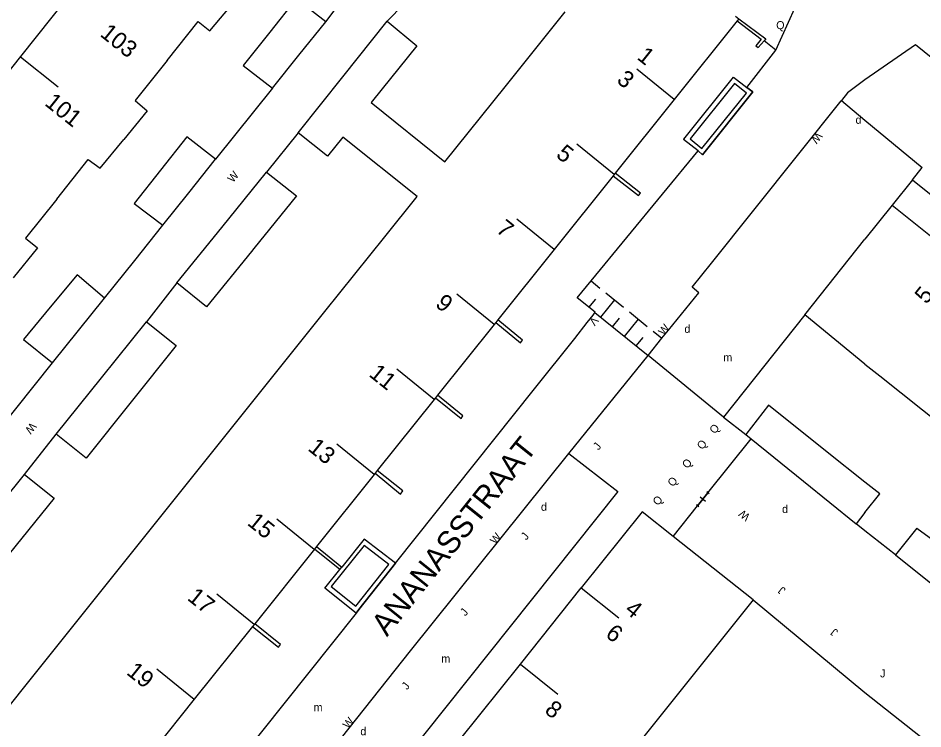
# Model space of a CAD drawing. Extents: x 134999 to 136502, y 457398 to 459002.
# Drawn here: x 135447.1 to 135503.6, y 457998 to 458042.3 of the extents above; entities that cross this region are included whole.
import ezdxf

# ---------------------------------------------------------------- set-up
doc = ezdxf.new("R2010")
doc.units = 0
for name, color, linetype in [('RI_DGTB_15', 7, 'Continuous'), ('RI_DGTB_29', 7, 'Continuous'), ('RI_DGTB_3', 7, 'Continuous'), ('RI_DGTB_30', 7, 'Continuous'), ('RI_DGTB_31', 7, 'Continuous'), ('RI_DGTB_35', 7, 'Continuous'), ('RI_DGTB_36', 7, 'Continuous'), ('RI_DGTB_37', 7, 'Continuous'), ('RI_DGTB_4', 7, 'Continuous'), ('RI_DGTB_43', 7, 'Continuous'), ('RI_DGTB_48', 7, 'Continuous'), ('RI_DGTB_5', 7, 'Continuous'), ('RI_DGTB_53', 7, 'Continuous'), ('RI_DGTB_54', 7, 'Continuous'), ('RI_DGTB_6', 7, 'Continuous')]:
    doc.layers.add(name, color=color, linetype=linetype)

msp = doc.modelspace()

# ---------------------------------------------------------------- linework, layer by layer
at = {"layer": 'RI_DGTB_15'}
for p, q in [((135447.257, 458039.913), (135449.6, 458038.04)), ((135488.09, 458037.25), (135485.749, 458039.126)), ((135484.342, 458032.569), (135482.001, 458034.445)), ((135480.594, 458027.888), (135478.253, 458029.764)), ((135476.846, 458023.207), (135474.505, 458025.083)), ((135473.098, 458018.526), (135470.757, 458020.402)), ((135469.35, 458013.845), (135467.009, 458015.721)), ((135465.602, 458009.164), (135463.261, 458011.04)), ((135482.275, 458006.757), (135484.619, 458004.884)), ((135461.854, 458004.483), (135459.513, 458006.359)), ((135458.106, 457999.802), (135455.765, 458001.678)), ((135478.476, 458002.005), (135480.82, 458000.132))]:
    msp.add_line(p, q, dxfattribs=at)
at = {"layer": 'RI_DGTB_3'}
for p, q in [((135501.696, 458030.642), (135500, 458028.523)), ((135501.696, 458030.642), (135506.429, 458026.857)), ((135500, 458020.732), (135500.934, 458019.985)), ((135500.934, 458019.985), (135505.666, 458016.202))]:
    msp.add_line(p, q, dxfattribs=at)
at = {"layer": 'RI_DGTB_31'}
for p, q in [((135492.988, 458037.71), (135489.857, 458033.797)), ((135492.614, 458037.993), (135492.988, 458037.71)), ((135488.673, 458034.74), (135488.694, 458034.766)), ((135489.591, 458034.029), (135488.673, 458034.74)), ((135489.857, 458033.797), (135489.591, 458034.029)), ((135482.894, 458025.924), (135483.447, 458025.475)), ((135482.761, 458024.252), (135483.197, 458024.789)), ((135483.499, 458023.654), (135484.37, 458024.728)), ((135483.816, 458025.176), (135484.923, 458024.279)), ((135483.137, 458023.947), (135486.451, 458021.261)), ((135484.237, 458023.056), (135484.672, 458023.593)), ((135485.292, 458023.98), (135486.399, 458023.083)), ((135484.975, 458022.458), (135485.845, 458023.531)), ((135486.768, 458022.784), (135487.321, 458022.335)), ((135485.713, 458021.86), (135486.148, 458022.396)), ((135470.678, 458008.298), (135468.393, 458005.41)), ((135468.393, 458005.41), (135468.21, 458005.179))]:
    msp.add_line(p, q, dxfattribs=at)
for points in [[(135488.694, 458034.766), (135491.78, 458038.639), (135492.614, 458037.993)], [(135489.079, 458034.783), (135489.82, 458034.191), (135492.601, 458037.629), (135491.853, 458038.247), (135489.079, 458034.783)], [(135470.678, 458008.298), (135468.724, 458009.8), (135467.326, 458008.058)], [(135466.658, 458006.836), (135468.19, 458005.619), (135470.255, 458008.221), (135468.723, 458009.413), (135466.658, 458006.836)], [(135468.21, 458005.179), (135466.264, 458006.735), (135467.202, 458007.904)]]:
    msp.add_lwpolyline(points, dxfattribs=at)
at = {"layer": 'RI_DGTB_4'}
for p, q in [((135450.7, 458044.243), (135447.245, 458039.922)), ((135477.517, 458038.039), (135481.267, 458042.718)), ((135491.91, 458042.449), (135492.12, 458042.282)), ((135492.12, 458042.282), (135492.019, 458042.156)), ((135492.019, 458042.156), (135488.09, 458037.25)), ((135447.245, 458039.922), (135443.791, 458035.602)), ((135473.767, 458033.359), (135477.517, 458038.039)), ((135488.09, 458037.25), (135484.401, 458032.642)), ((135484.401, 458032.642), (135484.342, 458032.57)), ((135484.276, 458032.486), (135480.594, 458027.888)), ((135484.342, 458032.57), (135484.276, 458032.486)), ((135466.268, 458024), (135470.017, 458028.679)), ((135496.252, 458023.792), (135500, 458028.523)), ((135480.594, 458027.888), (135477.066, 458023.482)), ((135462.518, 458019.32), (135466.268, 458024)), ((135500, 458020.732), (135496.252, 458023.792)), ((135476.846, 458023.207), (135473.297, 458018.778)), ((135476.941, 458023.326), (135476.846, 458023.207)), ((135477.066, 458023.482), (135476.941, 458023.326)), ((135458.768, 458014.64), (135462.518, 458019.32)), ((135473.096, 458018.527), (135469.537, 458014.079)), ((135473.165, 458018.613), (135473.096, 458018.527)), ((135473.297, 458018.778), (135473.165, 458018.613)), ((135455.019, 458009.961), (135458.768, 458014.64)), ((135469.537, 458014.079), (135469.402, 458013.91)), ((135469.35, 458013.845), (135465.743, 458009.34)), ((135469.402, 458013.91), (135469.35, 458013.845)), ((135451.268, 458005.281), (135455.019, 458009.961)), ((135493.016, 458006.014), (135488.019, 458009.966)), ((135465.618, 458009.184), (135461.883, 458004.521)), ((135465.743, 458009.34), (135465.618, 458009.184)), ((135478.477, 458002.004), (135482.277, 458006.756)), ((135493.016, 458006.014), (135489.184, 458001.237)), ((135447.519, 458000.602), (135451.268, 458005.281)), ((135461.883, 458004.521), (135461.74, 458004.342)), ((135461.74, 458004.342), (135458.105, 457999.803)), ((135474.678, 457997.252), (135478.477, 458002.004)), ((135489.184, 458001.237), (135485.376, 457996.491)), ((135443.769, 457995.922), (135447.519, 458000.602)), ((135458.105, 457999.803), (135454.357, 457995.122))]:
    msp.add_line(p, q, dxfattribs=at)
for points in [[(135470.017, 458028.679), (135472.027, 458031.187)], [(135488.019, 458009.966), (135486.074, 458011.505), (135482.277, 458006.756)]]:
    msp.add_lwpolyline(points, dxfattribs=at)
at = {"layer": 'RI_DGTB_48'}
for p, q in [((135467.202, 458007.904), (135465.618, 458009.184)), ((135465.743, 458009.34), (135467.326, 458008.058)), ((135467.202, 458007.904), (135467.326, 458008.058))]:
    msp.add_line(p, q, dxfattribs=at)
for points in [[(135492.12, 458042.282), (135493.815, 458041.027), (135493.712, 458040.906)], [(135492.019, 458042.156), (135493.519, 458040.999), (135493.191, 458040.591), (135493.335, 458040.477), (135493.712, 458040.906)], [(135484.276, 458032.486), (135485.862, 458031.242), (135485.987, 458031.397), (135484.401, 458032.642)], [(135476.941, 458023.326), (135478.492, 458022.053), (135478.618, 458022.215), (135477.066, 458023.482)], [(135473.165, 458018.613), (135474.771, 458017.335), (135474.886, 458017.487), (135473.297, 458018.778)], [(135469.402, 458013.91), (135470.992, 458012.611), (135471.145, 458012.808), (135469.537, 458014.079)], [(135461.74, 458004.342), (135463.363, 458003.069), (135463.485, 458003.234), (135461.883, 458004.521)]]:
    msp.add_lwpolyline(points, dxfattribs=at)
at = {"layer": 'RI_DGTB_5'}
for p, q in [((135469.147, 458037.061), (135473.767, 458033.359)), ((135472.027, 458031.187), (135467.395, 458034.898))]:
    msp.add_line(p, q, dxfattribs=at)
for points in [[(135456.415, 458039.674), (135458.353, 458042.104), (135459.076, 458041.518), (135460.649, 458043.371)], [(135456.415, 458039.674), (135454.416, 458037.169), (135455.168, 458036.53), (135453.712, 458034.753)], [(135449.516, 458031.025), (135451.488, 458033.497), (135452.239, 458032.954), (135453.712, 458034.753)], [(135449.516, 458031.025), (135447.574, 458028.589), (135448.313, 458027.983), (135446.806, 458026.11)]]:
    msp.add_lwpolyline(points, dxfattribs=at)
at = {"layer": 'RI_DGTB_53'}
for p, q in [((135490.409, 458027.036), (135498.502, 458037.149)), ((135498.527, 458037.181), (135500, 458035.96)), ((135500, 458035.96), (135503.576, 458032.995)), ((135502.963, 458032.227), (135501.696, 458030.642)), ((135496.252, 458023.792), (135491.165, 458017.412)), ((135491.165, 458017.412), (135492.565, 458016.341)), ((135490.193, 458012.686), (135492.899, 458016.07)), ((135489.549, 458011.88), (135490.194, 458012.687)), ((135490.193, 458012.686), (135489.549, 458011.88)), ((135490.033, 458012.154), (135489.709, 458012.412)), ((135490.274, 458012.623), (135490.114, 458012.751)), ((135488.019, 458009.966), (135489.549, 458011.88)), ((135489.629, 458011.816), (135489.469, 458011.944)), ((135500, 458010.325), (135499.442, 458010.767)), ((135501.904, 458008.818), (135500, 458010.325))]:
    msp.add_line(p, q, dxfattribs=at)
for points in [[(135506.201, 458038.203), (135503.146, 458040.643), (135500, 458038.47)], [(135502.963, 458032.227), (135540.814, 458001.934), (135539.56, 458000.364)]]:
    msp.add_lwpolyline(points, dxfattribs=at)
at = {"layer": 'RI_DGTB_54'}
for p, q in [((135466.321, 458042.095), (135469.789, 458046.684)), ((135494.441, 458040.321), (135493.712, 458040.906)), ((135492.614, 458037.993), (135494.441, 458040.321)), ((135462.987, 458037.941), (135459.441, 458033.511)), ((135489.857, 458033.797), (135492.988, 458037.71)), ((135492.988, 458037.71), (135492.614, 458037.993)), ((135498.502, 458037.149), (135498.527, 458037.181)), ((135464.604, 458035.17), (135462.622, 458032.713)), ((135488.673, 458034.74), (135488.694, 458034.766)), ((135489.591, 458034.029), (135489.857, 458033.797)), ((135502.963, 458032.227), (135503.576, 458032.995)), ((135454.404, 458027.2), (135456.144, 458029.398)), ((135452.506, 458024.842), (135454.404, 458027.2)), ((135489.204, 458025.53), (135490.409, 458027.036)), ((135457.021, 458025.793), (135455.128, 458023.374)), ((135445.634, 458016.287), (135449.255, 458020.803)), ((135481.502, 458015.147), (135486.451, 458021.261)), ((135491.165, 458017.412), (135486.451, 458021.261)), ((135447.507, 458013.838), (135449.482, 458016.346)), ((135468.393, 458005.41), (135470.678, 458008.298)), ((135493.016, 458006.014), (135500, 458000.229)), ((135468.21, 458005.179), (135468.393, 458005.41)), ((135500, 458000.229), (135504.365, 457996.786))]:
    msp.add_line(p, q, dxfattribs=at)
for points in [[(135494.441, 458040.321), (135496.809, 458045.594), (135496.966, 458047.987), (135494.208, 458050.252)], [(135470.992, 458045.337), (135470.019, 458044.154), (135471.204, 458043.201), (135470.165, 458042.122)], [(135500, 458038.47), (135498.908, 458037.66), (135498.527, 458037.181)], [(135482.894, 458025.924), (135489.591, 458034.029)], [(135483.157, 458023.974), (135482.017, 458024.863), (135482.894, 458025.924)], [(135487.73, 458022.839), (135489.622, 458025.173), (135489.204, 458025.53)], [(135470.678, 458008.298), (135479.367, 458019.191), (135481.876, 458022.315), (135482.653, 458023.322), (135483.016, 458023.784), (135483.157, 458023.974)], [(135487.321, 458022.335), (135487.73, 458022.839)], [(135486.451, 458021.261), (135487.321, 458022.335)], [(135481.502, 458015.147), (135484.555, 458012.773), (135461.76, 457984.216), (135458.729, 457986.601)], [(135462.605, 457991.477), (135471.61, 458002.822), (135481.502, 458015.147)], [(135468.21, 458005.179), (135459.351, 457994.078)]]:
    msp.add_lwpolyline(points, dxfattribs=at)
at = {"layer": 'RI_DGTB_6'}
for p, q in [((135464.49, 458031.237), (135461.828, 458027.931)), ((135492.565, 458016.341), (135492.899, 458016.07)), ((135500, 458011.469), (135499.442, 458010.767)), ((135503.24, 458010.484), (135506.79, 458007.883))]:
    msp.add_line(p, q, dxfattribs=at)
for points in [[(135466.321, 458042.095), (135464.481, 458043.539), (135462.82, 458041.454)], [(135464.642, 458040.003), (135466.321, 458042.095)], [(135467.384, 458038.646), (135470.165, 458042.122)], [(135470.165, 458042.122), (135472.014, 458040.6), (135469.233, 458037.167)], [(135462.82, 458041.454), (135461.16, 458039.37), (135462.987, 458037.941)], [(135462.987, 458037.941), (135464.642, 458040.003)], [(135464.604, 458035.17), (135467.384, 458038.646)], [(135469.233, 458037.167), (135469.147, 458037.061)], [(135459.441, 458033.511), (135457.652, 458034.909), (135456, 458032.83)], [(135467.395, 458034.898), (135466.427, 458033.704), (135464.604, 458035.17)], [(135457.768, 458031.425), (135459.441, 458033.511)], [(135456, 458032.83), (135454.348, 458030.75), (135456.144, 458029.398)], [(135459.822, 458029.253), (135462.622, 458032.713)], [(135462.622, 458032.713), (135464.49, 458031.237)], [(135456.144, 458029.398), (135457.768, 458031.425)], [(135457.021, 458025.793), (135459.822, 458029.253)], [(135461.68, 458027.749), (135458.877, 458024.295), (135457.021, 458025.793)], [(135461.828, 458027.931), (135461.68, 458027.749)], [(135452.506, 458024.842), (135450.784, 458026.303), (135449.11, 458024.283)], [(135450.878, 458022.82), (135452.506, 458024.842)], [(135449.11, 458024.283), (135447.437, 458022.263), (135449.255, 458020.803)], [(135452.305, 458019.86), (135455.128, 458023.374)], [(135455.128, 458023.374), (135456.972, 458021.883), (135454.164, 458018.369)], [(135449.255, 458020.803), (135450.878, 458022.82)], [(135449.482, 458016.346), (135452.305, 458019.86)], [(135454.164, 458018.369), (135451.351, 458014.848), (135449.482, 458016.346)], [(135497.643, 458015.235), (135493.979, 458018.159), (135492.565, 458016.341)], [(135492.899, 458016.07), (135496.17, 458013.419)], [(135500, 458013.355), (135497.643, 458015.235)], [(135444.7, 458010.365), (135447.507, 458013.838)], [(135447.507, 458013.838), (135449.356, 458012.366), (135446.545, 458008.874)], [(135496.17, 458013.419), (135499.442, 458010.767)], [(135500, 458011.469), (135500.918, 458012.623), (135500, 458013.355)], [(135503.24, 458010.484), (135501.904, 458008.818)], [(135501.904, 458008.818), (135505.371, 458006.046)]]:
    msp.add_lwpolyline(points, dxfattribs=at)

# ---------------------------------------------------------------- texts
at = {"layer": 'RI_DGTB_29'}
for p in [(135499.411, 458035.726), (135488.722, 458022.681), (135479.762, 458011.571), (135494.82, 458011.432), (135468.482, 457997.561)]:
    msp.add_text('d', height=0.5, dxfattribs=at).set_placement(p)
at = {"layer": 'RI_DGTB_30'}
for s, height, rotation, p in [('W', 0.5, 231.3952, (135496.991, 458035.243)), ('W', 0.5, 50.404, (135460.525, 458032.017)), ('V', 0.499, 231.3241, (135483.015, 458023.73)), ('W', 0.5, 51.3952, (135487.44, 458022.477)), ('W', 0.499, 231.2576, (135447.903, 458017.121)), ('W', 0.499, 141.5806, (135492.867, 458011.28)), ('W', 0.5, 51.3952, (135476.924, 458009.441)), ('W', 0.5, 51.3952, (135467.729, 457997.933))]:
    msp.add_text(s, height=height, rotation=rotation, dxfattribs=at).set_placement(p)
at = {"layer": 'RI_DGTB_31'}
for s, p in [('Q', (135494.454, 458041.632)), ('J', (135500.942, 458001.171))]:
    msp.add_text(s, height=0.5, dxfattribs=at).set_placement(p)
for s, height, rotation, p in [('Q', 0.5, 50.4006, (135490.62, 458016.331)), ('J', 0.5, 51.3952, (135483.358, 458015.32)), ('Q', 0.5, 50.4006, (135489.837, 458015.344)), ('Q', 0.5, 50.4006, (135488.906, 458014.168)), ('Q', 0.5, 50.4006, (135488.005, 458013.032)), ('Q', 0.5, 50.4006, (135487.073, 458011.857)), ('J', 0.5, 51.3952, (135478.848, 458009.704)), ('J', 0.499, 141.5806, (135495.085, 458006.678)), ('J', 0.5, 51.3952, (135475.049, 458004.968)), ('J', 0.499, 141.5806, (135498.364, 458004.067)), ('J', 0.5, 51.3952, (135471.402, 458000.358))]:
    msp.add_text(s, height=height, rotation=rotation, dxfattribs=at).set_placement(p)
at = {"layer": 'RI_DGTB_35'}
for s, rotation, p in [('1', 321.3168, (135485.704, 458039.805)), ('5', 51.3509, (135503.836, 458024.415)), ('4', 321.3581, (135484.934, 458005.275))]:
    msp.add_text(s, height=1.054, rotation=rotation, dxfattribs=at).set_placement(p)
at = {"layer": 'RI_DGTB_36'}
for s, rotation, p in [('103', 321.3509, (135452.164, 458041.244)), ('3', 321.3096, (135484.431, 458038.352)), ('101', 321.3509, (135448.708, 458036.925)), ('5', 321.3096, (135480.643, 458033.702)), ('7', 321.3096, (135476.901, 458029.016)), ('9', 321.3096, (135473.103, 458024.376)), ('11', 321.3096, (135468.96, 458020.012)), ('13', 321.3096, (135465.147, 458015.382)), ('15', 321.3096, (135461.359, 458010.734)), ('17', 321.3096, (135457.617, 458006.048)), ('6', 321.3581, (135483.728, 458003.767)), ('19', 321.3096, (135453.817, 458001.407)), ('8', 321.3581, (135479.929, 457999.015))]:
    msp.add_text(s, height=1.054, rotation=rotation, dxfattribs=at).set_placement(p)
at = {"layer": 'RI_DGTB_37'}
msp.add_text('ANANASSTRAAT', height=1.4, rotation=51.323, dxfattribs=at).set_placement((135470.145, 458003.669))
at = {"layer": 'RI_DGTB_43'}
for p in [(135491.151, 458020.894), (135473.54, 458002.094), (135465.562, 457999.057)]:
    msp.add_text('m', height=0.5, dxfattribs=at).set_placement(p)

doc.saveas('drawing.dxf')
